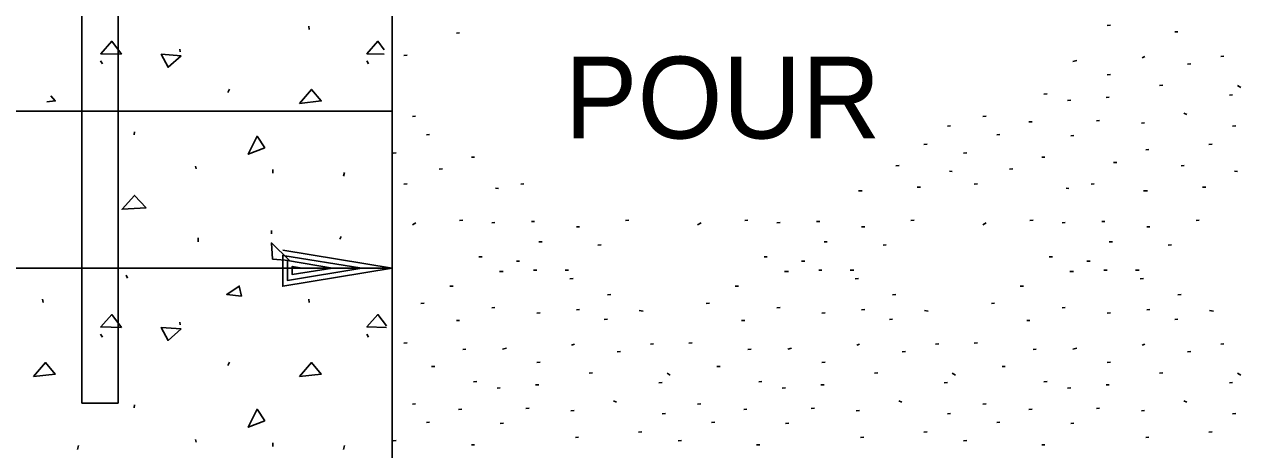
# Model space of a CAD drawing. Extents: x 0 to 320, y -4 to 473.
# Drawn here: x 32.485 to 34.567, y 15.094 to 15.822 of the extents above; entities that cross this region are included whole.
import ezdxf

# ---------------------------------------------------------------- set-up
doc = ezdxf.new("R2010")
doc.units = 0
for name, color, linetype in [('Level 10', 7, 'Continuous'), ('Level 2', 7, 'Continuous'), ('Level 3', 7, 'Continuous'), ('Level 44', 7, 'Continuous'), ('Level 50', 7, 'Continuous')]:
    doc.layers.add(name, color=color, linetype=linetype)

msp = doc.modelspace()

# ---------------------------------------------------------------- linework, layer by layer
at = {"layer": 'Level 10'}
for p, q in [((32.9724, 15.8133), (32.9714, 15.8193)), ((32.7514, 15.7752), (32.751, 15.7798)), ((32.6184, 15.7544), (32.6153, 15.7596)), ((33.0739, 15.7544), (33.0708, 15.7596)), ((32.833, 15.7057), (32.8358, 15.7112)), ((32.6726, 15.6331), (32.673, 15.6382)), ((32.7785, 15.5746), (32.7777, 15.5793)), ((32.9099, 15.5672), (32.9099, 15.5735)), ((33.0311, 15.5622), (33.0329, 15.5685)), ((32.9077, 15.4636), (32.9077, 15.4694)), ((32.7824, 15.4501), (32.7824, 15.4564)), ((33.0249, 15.4544), (33.0267, 15.4589)), ((32.6614, 15.3876), (32.6592, 15.3925)), ((32.5169, 15.3457), (32.5159, 15.3517)), ((32.9724, 15.3457), (32.9714, 15.3517)), ((32.7514, 15.3076), (32.751, 15.3122)), ((32.6184, 15.2868), (32.6153, 15.292)), ((33.0739, 15.2868), (33.0708, 15.292)), ((32.833, 15.2381), (32.8358, 15.2436)), ((32.6726, 15.1654), (32.673, 15.1706)), ((32.5756, 15.0946), (32.5774, 15.1009)), ((32.7785, 15.107), (32.7777, 15.1117)), ((32.9099, 15.0996), (32.9099, 15.1059)), ((33.0311, 15.0946), (33.0329, 15.1009))]:
    msp.add_line(p, q, dxfattribs=at)
for points in [[(32.6511, 15.7709), (32.6344, 15.7931), (32.6155, 15.7717)], [(32.753, 15.7685), (32.7308, 15.7487), (32.7189, 15.7709)], [(32.9558, 15.6869), (32.9764, 15.7107), (32.993, 15.691)], [(32.8963, 15.611), (32.8679, 15.5999), (32.8829, 15.6307)], [(32.693, 15.5079), (32.6732, 15.5294), (32.652, 15.5057)], [(32.9093, 15.4201), (32.9077, 15.4479), (32.9385, 15.4178)], [(32.8564, 15.3566), (32.8311, 15.3598), (32.8524, 15.3741)], [(32.6511, 15.3033), (32.6344, 15.3254), (32.6155, 15.3041)], [(32.753, 15.3009), (32.7308, 15.2811), (32.7189, 15.3033)], [(32.5003, 15.2193), (32.5209, 15.2431), (32.5375, 15.2234)], [(32.9558, 15.2193), (32.9764, 15.2431), (32.993, 15.2234)], [(32.8963, 15.1434), (32.8679, 15.1323), (32.8829, 15.1631)]]:
    msp.add_lwpolyline(points, close=True, dxfattribs=at)
for points in [[(33.1007, 15.7787), (33.0899, 15.7931), (33.071, 15.7717), (33.1008, 15.771)], [(32.5303, 15.6995), (32.5375, 15.691), (32.5233, 15.6894)], [(33.1047, 15.3059), (33.0899, 15.3254), (33.071, 15.3041), (33.1047, 15.3033)]]:
    msp.add_lwpolyline(points, dxfattribs=at)
at = {"layer": 'Level 2'}
for p, q in [((32.5828, 15.1736), (32.5828, 16.1736)), ((32.6453, 15.1736), (32.6453, 16.1736)), ((33.1141, 13.8403), (33.1141, 16.1319)), ((23.1141, 15.6736), (33.1141, 15.6736))]:
    msp.add_line(p, q, dxfattribs=at)
at = {"layer": 'Level 3'}
for p, q in [((33.2296, 15.8078), (33.2241, 15.8073)), ((34.3436, 15.8207), (34.3381, 15.8202)), ((34.4591, 15.8096), (34.4536, 15.8092)), ((33.1397, 15.7692), (33.1342, 15.7688)), ((34.2861, 15.7602), (34.2793, 15.7583)), ((34.4024, 15.7669), (34.3977, 15.7651)), ((34.5379, 15.7674), (34.5324, 15.7669)), ((34.4811, 15.7546), (34.4756, 15.7542)), ((34.3436, 15.7363), (34.3381, 15.7358)), ((34.2352, 15.7032), (34.2297, 15.7027)), ((34.3416, 15.6977), (34.3361, 15.6972)), ((34.4334, 15.7179), (34.4279, 15.7174)), ((34.5527, 15.7014), (34.5472, 15.7009)), ((34.5666, 15.7139), (34.5609, 15.7173)), ((34.2756, 15.6923), (34.2701, 15.6918)), ((33.1544, 15.6647), (33.1489, 15.6643)), ((34.1307, 15.6647), (34.1252, 15.6643)), ((34.3251, 15.6574), (34.3196, 15.6569)), ((34.4746, 15.6676), (34.4693, 15.6701)), ((34.0701, 15.6482), (34.0646, 15.6477)), ((34.2096, 15.6554), (34.2041, 15.6551)), ((34.4022, 15.6537), (34.3966, 15.6532)), ((34.5582, 15.6482), (34.5527, 15.6477)), ((33.1783, 15.6336), (33.1728, 15.6331)), ((34.0297, 15.6171), (34.0242, 15.6166)), ((34.1546, 15.6336), (34.1491, 15.6331)), ((34.2811, 15.6317), (34.2756, 15.6312)), ((34.5178, 15.6171), (34.5123, 15.6166)), ((33.1213, 15.6023), (33.1158, 15.6018)), ((33.2553, 15.5949), (33.2498, 15.5946)), ((34.0976, 15.6023), (34.0921, 15.6018)), ((34.2316, 15.5949), (34.2261, 15.5946)), ((34.4096, 15.6078), (34.4041, 15.6073)), ((33.2003, 15.5748), (33.1948, 15.5744)), ((33.9819, 15.5803), (33.9764, 15.5799)), ((34.1766, 15.5748), (34.1711, 15.5744)), ((34.3544, 15.5858), (34.3489, 15.5854)), ((34.4701, 15.5803), (34.4646, 15.5799)), ((34.0728, 15.5703), (34.0679, 15.5708)), ((34.5609, 15.5703), (34.5561, 15.5708)), ((33.1397, 15.5492), (33.1342, 15.5487)), ((33.2964, 15.5411), (33.2913, 15.5419)), ((33.3397, 15.5492), (33.3342, 15.5487)), ((33.9189, 15.5369), (33.9122, 15.5369)), ((34.0187, 15.5437), (34.0131, 15.5432)), ((34.1159, 15.5492), (34.1104, 15.5487)), ((34.2727, 15.5411), (34.2676, 15.5419)), ((34.3159, 15.5492), (34.3104, 15.5487)), ((34.4071, 15.5369), (34.4003, 15.5369)), ((34.5068, 15.5437), (34.5012, 15.5432)), ((33.1548, 15.4822), (33.1489, 15.4792)), ((33.2351, 15.4867), (33.2296, 15.4863)), ((33.2902, 15.4831), (33.2847, 15.4826)), ((33.3581, 15.4849), (33.3526, 15.4844)), ((33.4351, 15.4757), (33.4296, 15.4753)), ((33.5194, 15.4867), (33.5139, 15.4863)), ((33.6429, 15.4822), (33.6371, 15.4792)), ((33.7232, 15.4867), (33.7177, 15.4863)), ((33.7783, 15.4831), (33.7728, 15.4826)), ((33.8462, 15.4849), (33.8407, 15.4844)), ((33.9232, 15.4757), (33.9177, 15.4753)), ((34.0076, 15.4867), (34.0021, 15.4863)), ((34.1311, 15.4822), (34.1252, 15.4792)), ((34.2113, 15.4867), (34.2058, 15.4863)), ((34.2664, 15.4831), (34.2609, 15.4826)), ((34.3343, 15.4849), (34.3288, 15.4844)), ((34.4113, 15.4757), (34.4058, 15.4753)), ((34.4957, 15.4867), (34.4902, 15.4863)), ((33.3708, 15.4501), (33.3653, 15.4496)), ((33.8589, 15.4501), (33.8534, 15.4496)), ((34.3471, 15.4501), (34.3416, 15.4496)), ((33.4718, 15.4446), (33.4663, 15.4441)), ((33.9599, 15.4446), (33.9544, 15.4441)), ((34.4481, 15.4446), (34.4426, 15.4441)), ((33.2682, 15.4244), (33.2627, 15.4239)), ((33.3324, 15.4169), (33.3269, 15.4166)), ((33.7563, 15.4244), (33.7508, 15.4239)), ((33.8206, 15.4169), (33.8151, 15.4166)), ((34.2444, 15.4244), (34.2389, 15.4239)), ((34.3087, 15.4169), (34.3032, 15.4166)), ((33.1141, 15.4047), (31.6141, 15.4047)), ((33.3044, 15.3988), (33.2977, 15.3988)), ((33.3618, 15.4016), (33.3562, 15.4012)), ((33.4163, 15.4016), (33.4101, 15.4016)), ((33.4241, 15.3869), (33.4186, 15.3866)), ((33.7926, 15.3988), (33.7858, 15.3988)), ((33.8499, 15.4016), (33.8443, 15.4012)), ((33.9044, 15.4016), (33.8982, 15.4016)), ((33.9122, 15.3869), (33.9067, 15.3866)), ((34.2807, 15.3988), (34.2739, 15.3988)), ((34.3381, 15.4016), (34.3324, 15.4012)), ((34.3926, 15.4016), (34.3863, 15.4016)), ((34.4003, 15.3869), (34.3948, 15.3866)), ((33.2187, 15.3742), (33.2132, 15.3737)), ((33.7068, 15.3742), (33.7013, 15.3737)), ((34.1949, 15.3742), (34.1894, 15.3737)), ((33.1691, 15.3448), (33.1636, 15.3443)), ((33.4883, 15.3594), (33.4828, 15.3589)), ((33.6572, 15.3448), (33.6517, 15.3443)), ((33.9764, 15.3594), (33.9709, 15.3589)), ((34.1453, 15.3448), (34.1398, 15.3443)), ((34.4646, 15.3594), (34.4591, 15.3589)), ((33.2902, 15.3374), (33.2847, 15.3371)), ((33.3673, 15.3283), (33.3618, 15.3278)), ((33.4351, 15.3338), (33.4296, 15.3333)), ((33.5437, 15.3313), (33.5372, 15.3323)), ((33.7783, 15.3374), (33.7728, 15.3371)), ((33.8554, 15.3283), (33.8499, 15.3278)), ((33.9232, 15.3338), (33.9177, 15.3333)), ((34.0318, 15.3313), (34.0253, 15.3323)), ((34.2664, 15.3374), (34.2609, 15.3371)), ((34.3436, 15.3283), (34.3381, 15.3278)), ((34.4113, 15.3338), (34.4058, 15.3333)), ((34.5199, 15.3313), (34.5134, 15.3323)), ((33.2296, 15.3154), (33.2241, 15.3149)), ((33.4828, 15.3172), (33.4773, 15.3168)), ((33.7177, 15.3154), (33.7122, 15.3149)), ((33.9709, 15.3172), (33.9654, 15.3168)), ((34.2058, 15.3154), (34.2003, 15.3149)), ((34.4591, 15.3172), (34.4536, 15.3168)), ((33.1397, 15.2768), (33.1342, 15.2764)), ((33.2406, 15.2659), (33.2351, 15.2654)), ((33.3098, 15.2678), (33.3031, 15.2659)), ((33.4262, 15.2746), (33.4214, 15.2727)), ((33.5048, 15.2622), (33.4993, 15.2618)), ((33.5617, 15.2751), (33.5562, 15.2746)), ((33.6278, 15.2768), (33.6223, 15.2764)), ((33.7287, 15.2659), (33.7232, 15.2654)), ((33.7979, 15.2678), (33.7912, 15.2659)), ((33.9143, 15.2746), (33.9096, 15.2727)), ((33.9929, 15.2622), (33.9874, 15.2618)), ((34.0498, 15.2751), (34.0443, 15.2746)), ((34.1159, 15.2768), (34.1104, 15.2764)), ((34.2168, 15.2659), (34.2113, 15.2654)), ((34.2861, 15.2678), (34.2793, 15.2659)), ((34.4024, 15.2746), (34.3977, 15.2727)), ((34.4811, 15.2622), (34.4756, 15.2618)), ((34.5379, 15.2751), (34.5324, 15.2746)), ((33.3673, 15.2439), (33.3618, 15.2434)), ((33.8554, 15.2439), (33.8499, 15.2434)), ((34.3436, 15.2439), (34.3381, 15.2434)), ((33.1874, 15.2366), (33.1818, 15.2362)), ((33.4572, 15.2256), (33.4517, 15.2251)), ((33.5903, 15.2216), (33.5847, 15.2249)), ((33.6756, 15.2366), (33.6699, 15.2362)), ((33.9453, 15.2256), (33.9398, 15.2251)), ((34.0784, 15.2216), (34.0728, 15.2249)), ((34.1637, 15.2366), (34.1581, 15.2362)), ((34.4334, 15.2256), (34.4279, 15.2251)), ((34.5666, 15.2216), (34.5609, 15.2249)), ((33.2589, 15.2108), (33.2534, 15.2103)), ((33.2993, 15.1999), (33.2938, 15.1994)), ((33.3653, 15.2053), (33.3598, 15.2048)), ((33.5764, 15.2091), (33.5709, 15.2086)), ((33.7471, 15.2108), (33.7416, 15.2103)), ((33.7874, 15.1999), (33.7819, 15.1994)), ((33.8534, 15.2053), (33.8479, 15.2048)), ((34.0646, 15.2091), (34.0591, 15.2086)), ((34.2352, 15.2108), (34.2297, 15.2103)), ((34.2756, 15.1999), (34.2701, 15.1994)), ((34.3416, 15.2053), (34.3361, 15.2048)), ((34.5527, 15.2091), (34.5472, 15.2086)), ((33.4983, 15.1752), (33.4931, 15.1777)), ((33.9864, 15.1752), (33.9812, 15.1777)), ((34.4746, 15.1752), (34.4693, 15.1777)), ((33.1544, 15.1723), (33.1489, 15.1719)), ((33.2333, 15.1631), (33.2278, 15.1627)), ((33.3488, 15.1651), (33.3433, 15.1646)), ((33.4259, 15.1613), (33.4203, 15.1608)), ((33.6426, 15.1723), (33.6371, 15.1719)), ((33.7214, 15.1631), (33.7159, 15.1627)), ((33.8369, 15.1651), (33.8314, 15.1646)), ((33.9141, 15.1613), (33.9084, 15.1608)), ((34.1307, 15.1723), (34.1252, 15.1719)), ((34.2096, 15.1631), (34.2041, 15.1627)), ((34.3251, 15.1651), (34.3196, 15.1646)), ((34.4022, 15.1613), (34.3966, 15.1608)), ((33.1783, 15.1412), (33.1728, 15.1407)), ((33.3048, 15.1393), (33.2993, 15.1388)), ((33.5819, 15.1558), (33.5764, 15.1553)), ((33.6664, 15.1412), (33.6609, 15.1407)), ((33.7929, 15.1393), (33.7874, 15.1388)), ((34.0701, 15.1558), (34.0646, 15.1553)), ((34.1546, 15.1412), (34.1491, 15.1407)), ((34.2811, 15.1393), (34.2756, 15.1388)), ((34.5582, 15.1558), (34.5527, 15.1553)), ((33.4333, 15.1154), (33.4278, 15.1149)), ((33.5416, 15.1247), (33.5361, 15.1242)), ((33.9214, 15.1154), (33.9159, 15.1149)), ((34.0297, 15.1247), (34.0242, 15.1242)), ((34.4096, 15.1154), (34.4041, 15.1149)), ((34.5178, 15.1247), (34.5123, 15.1242)), ((33.1213, 15.1099), (33.1158, 15.1094)), ((33.2553, 15.1026), (33.2498, 15.1022)), ((33.6094, 15.1099), (33.6039, 15.1094)), ((33.7434, 15.1026), (33.7379, 15.1022)), ((34.0976, 15.1099), (34.0921, 15.1094)), ((34.2316, 15.1026), (34.2261, 15.1022))]:
    msp.add_line(p, q, dxfattribs=at)
at = {"layer": 'Level 44'}
msp.add_line((32.5828, 15.1736), (32.6453, 15.1736), dxfattribs=at)
at = {"layer": 'Level 50'}
for p, q in [((33.0621, 15.4047), (33.0621, 15.4047)), ((33.1141, 15.4047), (33.1141, 15.4047))]:
    msp.add_line(p, q, dxfattribs=at)
msp.add_lwpolyline([(32.9271, 15.4357), (33.1141, 15.4047), (32.9271, 15.3737), (32.9271, 15.4267), (33.0621, 15.4047), (32.9351, 15.3837), (32.9351, 15.4177), (33.0121, 15.4047), (32.9431, 15.3937), (32.9431, 15.4077), (32.9601, 15.4047)], dxfattribs=at)

# ---------------------------------------------------------------- texts
at = {"layer": 'Level 3'}
msp.add_text('POUR', height=0.14, dxfattribs=at).set_placement((33.4093, 15.6268))

doc.saveas('drawing.dxf')
